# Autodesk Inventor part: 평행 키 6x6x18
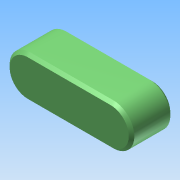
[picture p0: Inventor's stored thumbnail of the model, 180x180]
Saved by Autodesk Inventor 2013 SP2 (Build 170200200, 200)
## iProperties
Created: 2026-10
Part Number: 평행 키 6x6x18
Material: Generic
Document SubType Name: Modeling
Designer: a
Density: 1 g/cm^3
Author: a
변환 표준: STEP AP214IS
전처리기: Build: 200, Release: 2013 SP2 Update 6 - Date: Thu 07/17/2014
전송 단위: 밀리미터
불확실성: 0.01
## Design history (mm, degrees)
node "평행 키 6x6x181"
body "Solid1"
node "기준1"
